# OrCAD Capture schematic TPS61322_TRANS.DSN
size C; title: TPS61322xx 1.8-A Switch Current Boost Converter; rev: 1.0; note: DATASHEET: SNVSAH5 NOVEMBER 2015
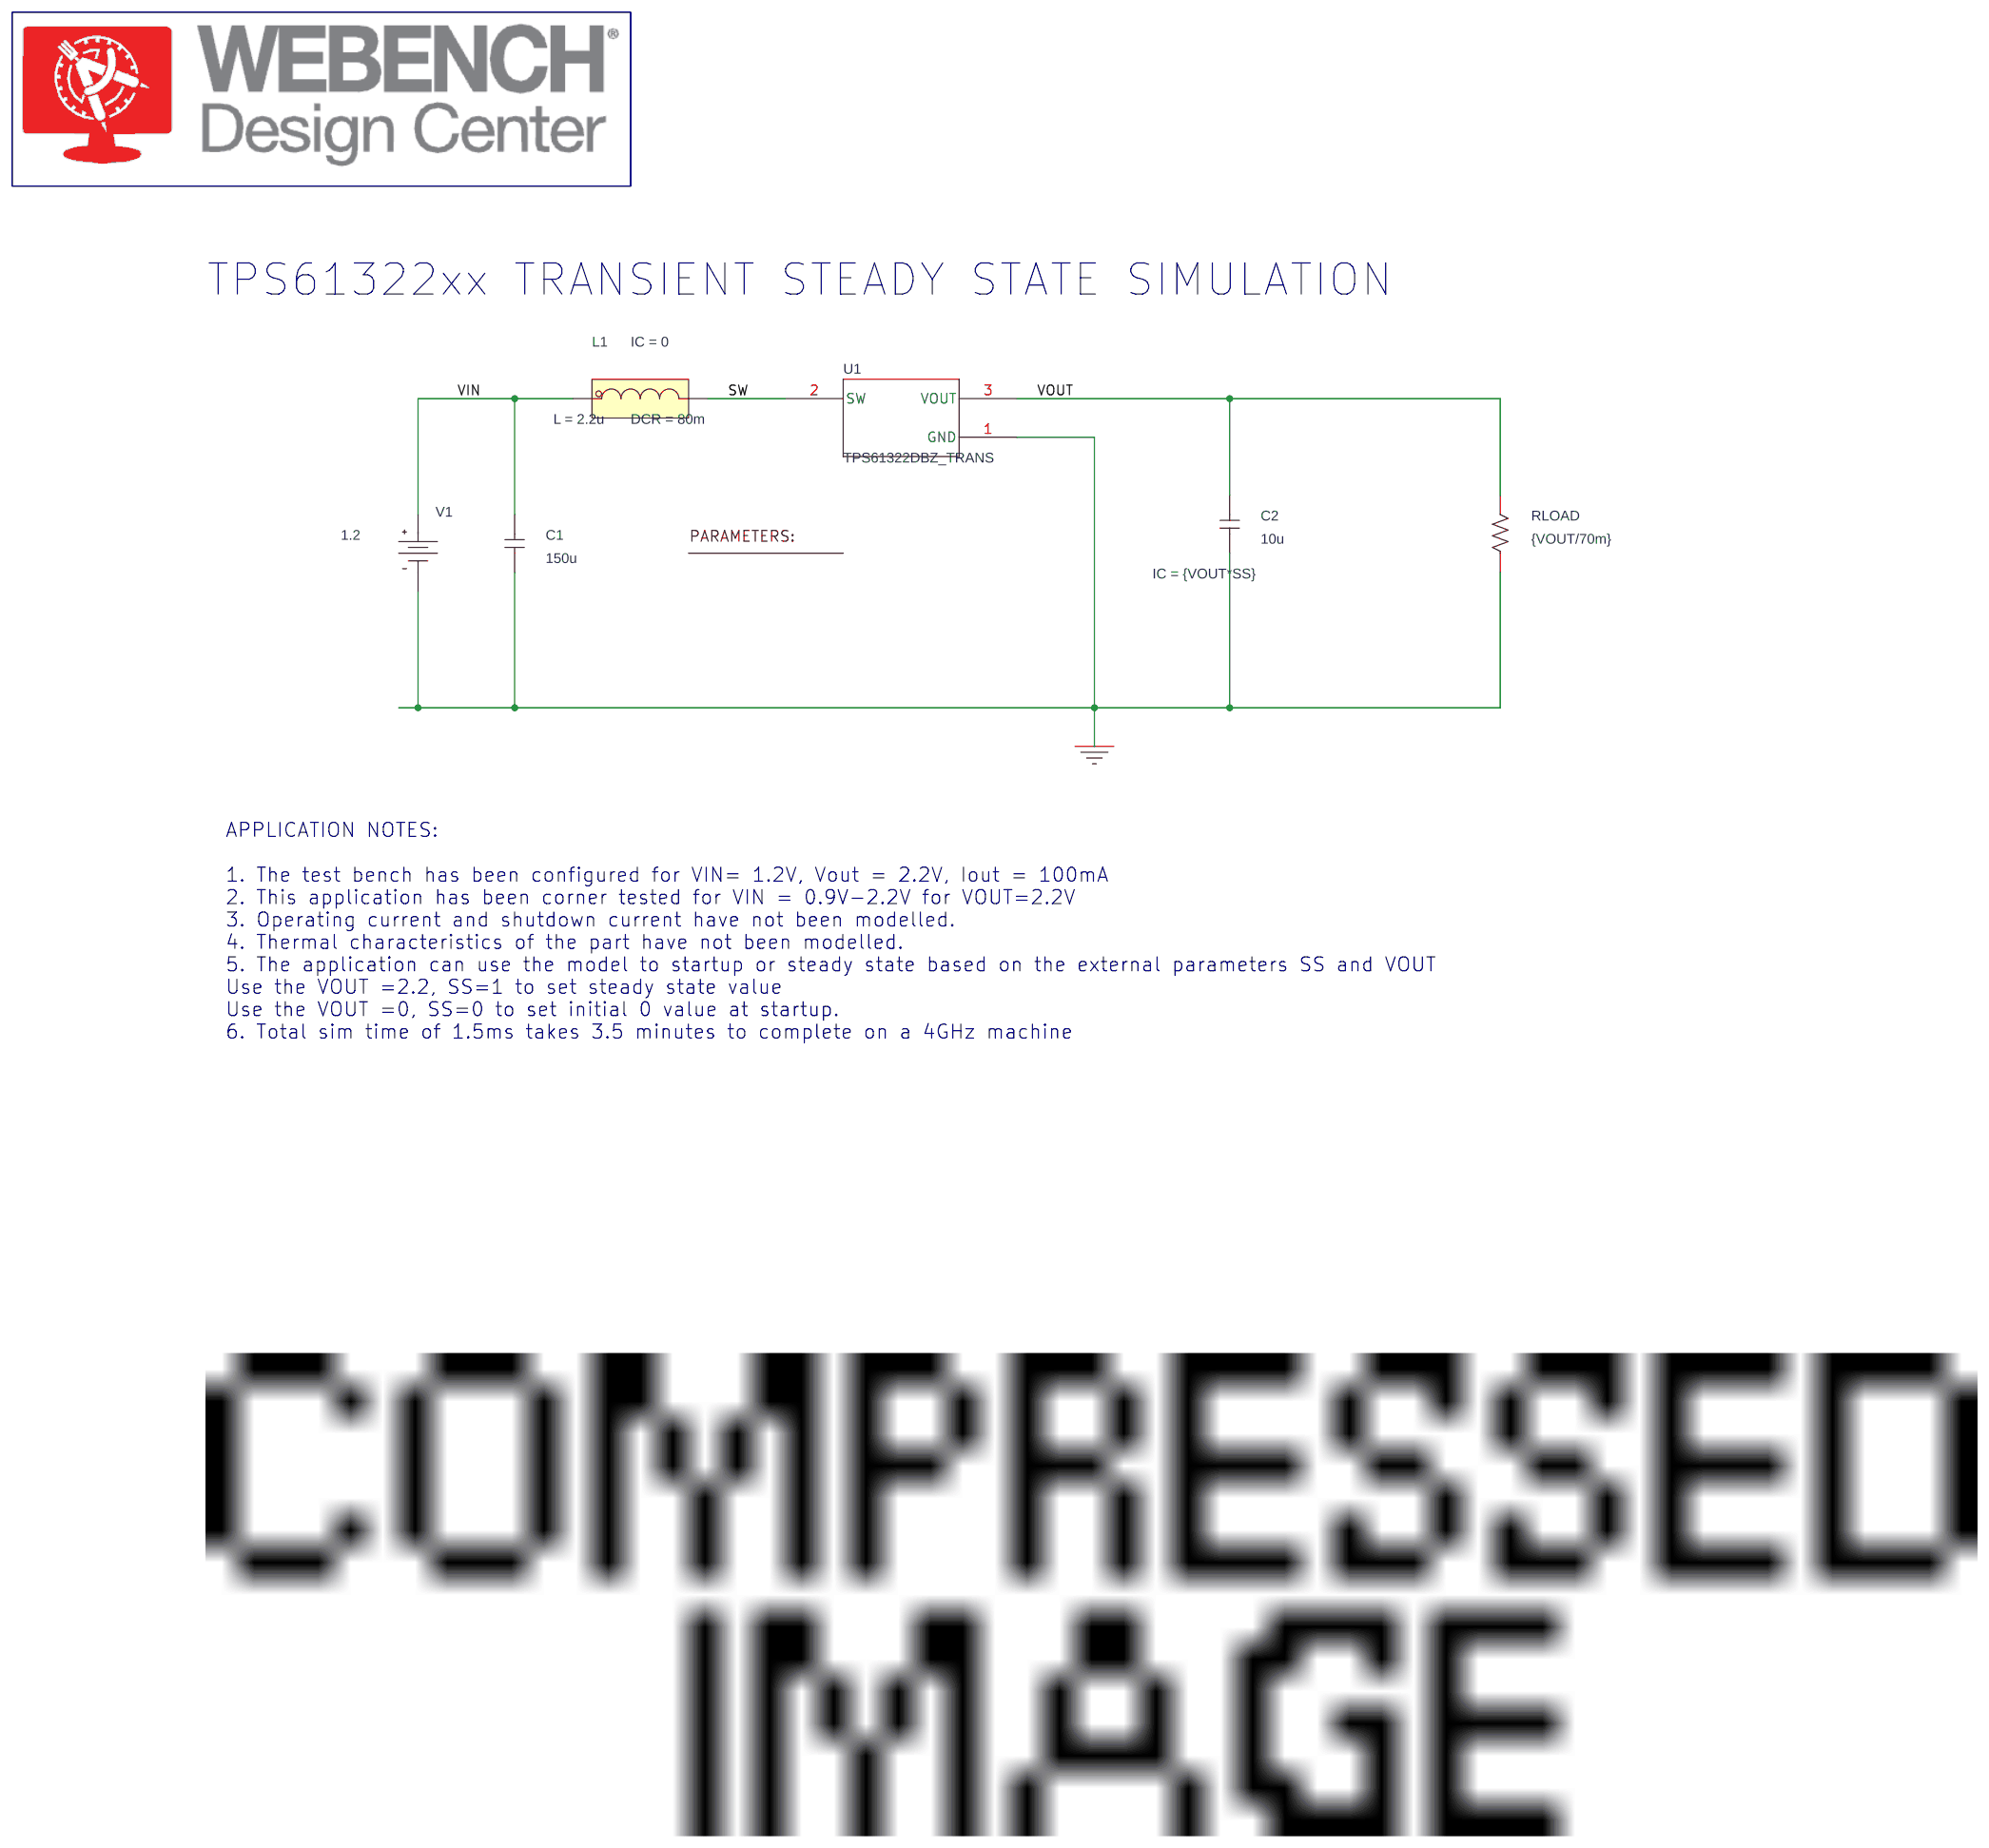
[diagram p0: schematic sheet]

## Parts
1  PARAM
C1  150u  [RAD/CK05]
C2  10u  [RAD/CK05]
L1  LDCR
RLOAD  {VOUT/70m}  [AX/RC05]
U1  TPS61322DBZ_TRANS  [DBZ0003A_N]
V1  VDC

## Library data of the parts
1 = PARAM: VOUT: 2.2
C1 = C
C2 = C: IC: {VOUT*SS}
L1 = LDCR: DCR: 80m; IC: 0; L: 2.2u; PSpiceTemplate: X^@REFDES %IN %OUT @MODEL PARAMS:  ?L|L=@L||L=1u|  ?DCR|DCR=@DCR||DCR=0.01| ?IC|IC=@IC||IC=0|
RLOAD = R
U1 = TPS61322DBZ_TRANS
V1 = VDC: DC: 1.2

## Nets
VIN: C1.1 L1.1(IN) V1.0(+)
0: C1.2 C2.2 RLOAD.1 U1.1(GND) V1.1(-)
SW: L1.3(OUT) U1.2(SW)
VOUT: C2.1 RLOAD.2 U1.3(VOUT)

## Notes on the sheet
- TPS61322xx TRANSIENT STEADY STATE SIMULATION
- APPLICATION NOTES:
  1. The test bench has been configured for VIN= 1.2V, Vout = 2.2V, Iout = 100mA
  2. This application has been corner tested for VIN = 0.9V-2.2V for VOUT=2.2V
  3. Operating current and shutdown current have not been modelled.
  4. Thermal characteristics of the part have not been modelled.
  5. The application can use the model to startup or steady state based on the external parameters SS and VOUT
  Use the VOUT =2.2, SS=1 to set steady state value
  Use the VOUT =0, SS=0 to set initial 0 value at startup.
  6. Total sim time of 1.5ms takes 3.5 minutes to complete on a 4GHz machine
